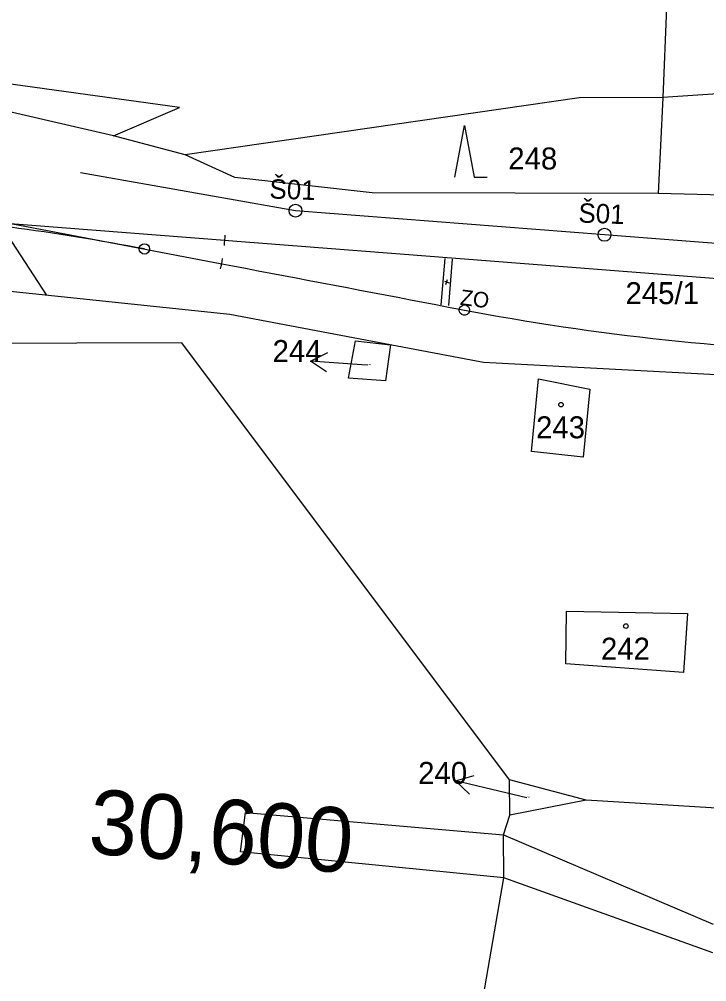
# Model space of a CAD drawing. Extents: x -670359 to -668019, y -978807 to -976674.
# Drawn here: x -669575.5 to -669522.2, y -977191.2 to -977116.7 of the extents above; entities that cross this region are included whole.
import ezdxf

# ---------------------------------------------------------------- set-up
doc = ezdxf.new("R2010")
doc.units = 0
for name, color, linetype in [('Hranice parcel', 7, 'Continuous'), ('Parcelní čísla', 7, 'Continuous'), ('SO 01-86-01', 7, 'Continuous'), ('SO 11-10-01', 7, 'Continuous'), ('SO 11-11-01', 7, 'Continuous'), ('Vnitřní kresba', 7, 'Continuous'), ('Značky budov', 7, 'Continuous'), ('Značky kultur', 7, 'Continuous')]:
    doc.layers.add(name, color=color, linetype=linetype)

# ---------------------------------------------------------------- blocks, each defined once
blk = doc.blocks.new('POINT_DISPLAY')
blk.add_line((0, 0), (0, 0))

msp = doc.modelspace()

# ---------------------------------------------------------------- linework, layer by layer
at = {"layer": 'Hranice parcel'}
for points in [[(-669523.39, -977067.04), (-669525.65, -977122.76)], [(-669563.07, -977123.54), (-669592.04, -977119.56)], [(-669495.11, -977120.74), (-669525.65, -977122.76)], [(-669568.18, -977125.73), (-669579.07, -977123.23)], [(-669532.13, -977122.79), (-669562.65, -977127.21)], [(-669525.65, -977122.76), (-669532.13, -977122.79)], [(-669525.65, -977122.76), (-669526.01, -977130.19)], [(-669568.18, -977125.73), (-669563.07, -977123.54)], [(-669562.65, -977127.21), (-669568.18, -977125.73)], [(-669558.8, -977128.95), (-669562.65, -977127.21)], [(-669548.16, -977130.16), (-669558.8, -977128.95)], [(-669526.01, -977130.19), (-669548.16, -977130.16)], [(-669495.86, -977130.97), (-669526.01, -977130.19)], [(-669562.89, -977141.76), (-669619.92, -977141.93)], [(-669537.52, -977175.57), (-669562.89, -977141.76)], [(-669550, -977144.48), (-669549.46, -977141.6)], [(-669549.46, -977141.6), (-669546.74, -977141.9)], [(-669546.74, -977141.9), (-669547.12, -977144.7)], [(-669547.12, -977144.7), (-669550, -977144.48)], [(-669535.82, -977150.15), (-669535.29, -977144.55)], [(-669535.29, -977144.55), (-669531.29, -977145.33)], [(-669531.29, -977145.33), (-669531.82, -977150.6)], [(-669531.82, -977150.6), (-669535.82, -977150.15)], [(-669533.17, -977166.59), (-669533.11, -977162.52)], [(-669533.11, -977162.52), (-669523.75, -977162.7)], [(-669523.75, -977162.7), (-669524.05, -977167.26)], [(-669524.05, -977167.26), (-669533.17, -977166.59)], [(-669531.59, -977177.13), (-669537.52, -977175.57)], [(-669537.5, -977178.29), (-669537.52, -977175.57)], [(-669531.59, -977177.13), (-669537.5, -977178.29)], [(-669512.22, -977178.33), (-669531.59, -977177.13)], [(-669537.98, -977179.81), (-669537.5, -977178.29)], [(-669537.96, -977183.16), (-669537.98, -977179.81)], [(-669544.29, -977219.72), (-669537.96, -977183.16)]]:
    msp.add_lwpolyline(points, dxfattribs=at)
at = {"layer": 'Parcelní čísla'}
for p, q in [((-669551.696, -977144.01), (-669552.94, -977143.172)), ((-669548.5, -977143.48), (-669548.95, -977143.45)), ((-669540.62, -977176.682), (-669541.71, -977175.65)), ((-669536.18, -977176.97), (-669537.82, -977176.58))]:
    msp.add_line(p, q, dxfattribs=at)
for points in [[(-669548.95, -977143.45), (-669552.94, -977143.172), (-669551.591, -977142.514)], [(-669537.82, -977176.58), (-669541.71, -977175.65), (-669540.272, -977175.223)]]:
    msp.add_lwpolyline(points, dxfattribs=at)
at = {"layer": 'SO 01-86-01'}
for p, q in [((-669576.696, -977132.957), (-669573.41, -977138.033)), ((-669584.138, -977136.927), (-669559.186, -977139.528)), ((-669559.186, -977139.528), (-669539.545, -977143.259)), ((-669539.545, -977143.259), (-669520.014, -977144.295))]:
    msp.add_line(p, q, dxfattribs=at)
at = {"layer": 'SO 11-10-01'}
for p, q in [((-669586.625, -977131.706), (-669559.568, -977133.813)), ((-669576.133, -977132.523), (-669559.812, -977135.634)), ((-669559.568, -977133.813), (-669559.289, -977133.834)), ((-669559.289, -977133.834), (-669558.292, -977133.912)), ((-669558.292, -977133.912), (-669557.295, -977133.989)), ((-669557.295, -977133.989), (-669556.298, -977134.067)), ((-669556.298, -977134.067), (-669555.301, -977134.145)), ((-669555.301, -977134.145), (-669554.304, -977134.222)), ((-669554.304, -977134.222), (-669553.307, -977134.3)), ((-669553.307, -977134.3), (-669552.31, -977134.378)), ((-669552.31, -977134.378), (-669551.313, -977134.455)), ((-669551.313, -977134.455), (-669550.316, -977134.533)), ((-669550.316, -977134.533), (-669549.319, -977134.61)), ((-669549.319, -977134.61), (-669548.322, -977134.688)), ((-669548.322, -977134.688), (-669547.325, -977134.766)), ((-669547.325, -977134.766), (-669546.328, -977134.843)), ((-669546.328, -977134.843), (-669545.331, -977134.921)), ((-669545.331, -977134.921), (-669544.335, -977134.998)), ((-669544.335, -977134.998), (-669543.338, -977135.076)), ((-669543.338, -977135.076), (-669542.341, -977135.154)), ((-669542.341, -977135.154), (-669541.344, -977135.231)), ((-669559.812, -977135.634), (-669558.944, -977135.799)), ((-669558.944, -977135.799), (-669557.962, -977135.987)), ((-669542.525, -977135.217), (-669542.832, -977138.803)), ((-669542.231, -977138.855), (-669541.925, -977135.27)), ((-669541.344, -977135.231), (-669540.347, -977135.309)), ((-669540.347, -977135.309), (-669539.35, -977135.386)), ((-669539.35, -977135.386), (-669538.353, -977135.464)), ((-669538.353, -977135.464), (-669537.356, -977135.542)), ((-669537.356, -977135.542), (-669536.359, -977135.619)), ((-669536.359, -977135.619), (-669535.362, -977135.697)), ((-669535.362, -977135.697), (-669534.365, -977135.774)), ((-669534.365, -977135.774), (-669533.368, -977135.852)), ((-669533.368, -977135.852), (-669532.371, -977135.93)), ((-669557.962, -977135.987), (-669556.98, -977136.174)), ((-669556.98, -977136.174), (-669555.997, -977136.361)), ((-669555.997, -977136.361), (-669555.015, -977136.548)), ((-669555.015, -977136.548), (-669554.033, -977136.735)), ((-669532.371, -977135.93), (-669531.374, -977136.007)), ((-669531.374, -977136.007), (-669530.377, -977136.085)), ((-669530.377, -977136.085), (-669529.38, -977136.162)), ((-669529.38, -977136.162), (-669528.383, -977136.24)), ((-669528.383, -977136.24), (-669527.386, -977136.318)), ((-669527.386, -977136.318), (-669526.389, -977136.395)), ((-669526.389, -977136.395), (-669525.392, -977136.473)), ((-669525.392, -977136.473), (-669524.395, -977136.55)), ((-669524.395, -977136.55), (-669523.398, -977136.628)), ((-669523.398, -977136.628), (-669522.401, -977136.706)), ((-669554.033, -977136.735), (-669553.05, -977136.923)), ((-669553.05, -977136.923), (-669552.068, -977137.11)), ((-669552.068, -977137.11), (-669551.086, -977137.297)), ((-669551.086, -977137.297), (-669550.103, -977137.484)), ((-669542.568, -977136.975), (-669542.189, -977137.106)), ((-669542.445, -977137.231), (-669542.317, -977136.851)), ((-669522.401, -977136.706), (-669521.404, -977136.783)), ((-669550.103, -977137.484), (-669549.121, -977137.672)), ((-669549.121, -977137.672), (-669548.139, -977137.859)), ((-669548.139, -977137.859), (-669547.156, -977138.046)), ((-669547.156, -977138.046), (-669546.174, -977138.233)), ((-669546.174, -977138.233), (-669545.192, -977138.421)), ((-669545.192, -977138.421), (-669544.21, -977138.608)), ((-669544.21, -977138.608), (-669543.227, -977138.795)), ((-669543.227, -977138.795), (-669542.245, -977138.982)), ((-669542.245, -977138.982), (-669541.263, -977139.169)), ((-669541.263, -977139.169), (-669541.016, -977139.217)), ((-669541.016, -977139.217), (-669540.28, -977139.355)), ((-669540.28, -977139.355), (-669539.296, -977139.536)), ((-669539.296, -977139.536), (-669538.312, -977139.712)), ((-669538.312, -977139.712), (-669537.327, -977139.882)), ((-669537.327, -977139.882), (-669536.34, -977140.047)), ((-669536.34, -977140.047), (-669535.353, -977140.207)), ((-669535.353, -977140.207), (-669534.365, -977140.362)), ((-669534.365, -977140.362), (-669533.377, -977140.512)), ((-669533.377, -977140.512), (-669532.387, -977140.656)), ((-669532.387, -977140.656), (-669531.397, -977140.795)), ((-669531.397, -977140.795), (-669530.406, -977140.929)), ((-669530.406, -977140.929), (-669529.414, -977141.058)), ((-669529.414, -977141.058), (-669528.422, -977141.182)), ((-669528.422, -977141.182), (-669527.429, -977141.3)), ((-669527.429, -977141.3), (-669526.435, -977141.413)), ((-669526.435, -977141.413), (-669525.441, -977141.521)), ((-669525.441, -977141.521), (-669524.446, -977141.624)), ((-669524.446, -977141.624), (-669523.451, -977141.721)), ((-669523.451, -977141.721), (-669522.455, -977141.813)), ((-669522.455, -977141.813), (-669521.459, -977141.9))]:
    msp.add_line(p, q, dxfattribs=at)
msp.add_lwpolyline([(-669541.09, -977139.61), (-669541.216, -977139.558), (-669541.332, -977139.455), (-669541.396, -977139.361), (-669541.423, -977139.22), (-669541.393, -977139.063), (-669541.321, -977138.968), (-669541.223, -977138.879), (-669541.077, -977138.825), (-669540.941, -977138.824), (-669540.815, -977138.875), (-669540.699, -977138.978), (-669540.635, -977139.072), (-669540.608, -977139.213), (-669540.638, -977139.37), (-669540.71, -977139.465), (-669540.808, -977139.555), (-669540.954, -977139.608), (-669541.09, -977139.61)], dxfattribs=at)
msp.add_circle((-669565.796, -977134.493), 0.4, dxfattribs=at)
for centre, radius, start, end in [((-669601.37, -977321.133), 190, 79.209, 85.54903), ((-669576.134, -977132.523), 16.616, 354.16966, 356.92839), ((-669576.134, -977132.523), 16.616, 347.82947, 350.5882)]:
    msp.add_arc(centre, radius, start, end, dxfattribs=at)
at = {"layer": 'SO 11-11-01'}
for p, q in [((-669554.095, -977131.53), (-669570.744, -977128.591)), ((-669530.167, -977133.393), (-669554.095, -977131.53)), ((-669495.771, -977136.07), (-669530.167, -977133.393))]:
    msp.add_line(p, q, dxfattribs=at)
for centre in [(-669554.095, -977131.53), (-669530.167, -977133.393)]:
    msp.add_circle(centre, 0.5, dxfattribs=at)
at = {"layer": 'Vnitřní kresba'}
for points in [[(-669558.36, -977181.13), (-669557.98, -977178.09)], [(-669557.98, -977178.09), (-669537.98, -977179.81)], [(-669537.98, -977179.81), (-669521.74, -977186.74)], [(-669537.96, -977183.16), (-669558.36, -977181.13)], [(-669521.77, -977188.94), (-669537.96, -977183.16)]]:
    msp.add_lwpolyline(points, dxfattribs=at)
at = {"layer": 'Značky budov'}
for centre in [(-669533.54, -977146.54), (-669528.51, -977163.67)]:
    msp.add_circle(centre, 0.175, dxfattribs=at)
at = {"layer": 'Značky kultur'}
msp.add_lwpolyline([(-669541.76, -977128.93), (-669541.01, -977124.93), (-669540.26, -977128.93), (-669539.26, -977128.93)], dxfattribs=at)
for centre in [(-669533.54, -977146.54), (-669528.51, -977163.67)]:
    msp.add_circle(centre, 0.175, dxfattribs=at)

# ---------------------------------------------------------------- block references
at = {"layer": 'SO 11-10-01'}
msp.add_blockref('POINT_DISPLAY', (-669565.796, -977134.493), dxfattribs=at)

# ---------------------------------------------------------------- texts
at = {"layer": 'Parcelní čísla'}
for s, height, p in [('248', 1.7, (-669537.619, -977128.34)), ('245/1', 1.7, (-669528.54, -977138.76)), ('244', 1.7, (-669555.869, -977143.24)), ('244', 0.1, (-669548.5, -977143.48)), ('243', 1.7, (-669535.469, -977149.14)), ('242', 1.7, (-669530.439, -977166.27)), ('240', 1.7, (-669544.597, -977175.88)), ('240', 0.1, (-669536.18, -977176.97))]:
    msp.add_text(s, height=height, dxfattribs=at).set_placement(p)
at = {"layer": 'SO 11-10-01'}
for s, height, rotation, p in [('ZO', 1.2, 352.80685, (-669541.389, -977138.806)), ('30,600', 5, 355.63914, (-669570.216, -977181.248))]:
    msp.add_text(s, height=height, rotation=rotation, dxfattribs=at).set_placement(p)
at = {"layer": 'SO 11-11-01'}
for p in [(-669556.131, -977130.581), (-669532.204, -977132.443)]:
    msp.add_text('Š01', height=1.5, rotation=357.94491, dxfattribs=at).set_placement(p)

doc.saveas('drawing.dxf')
